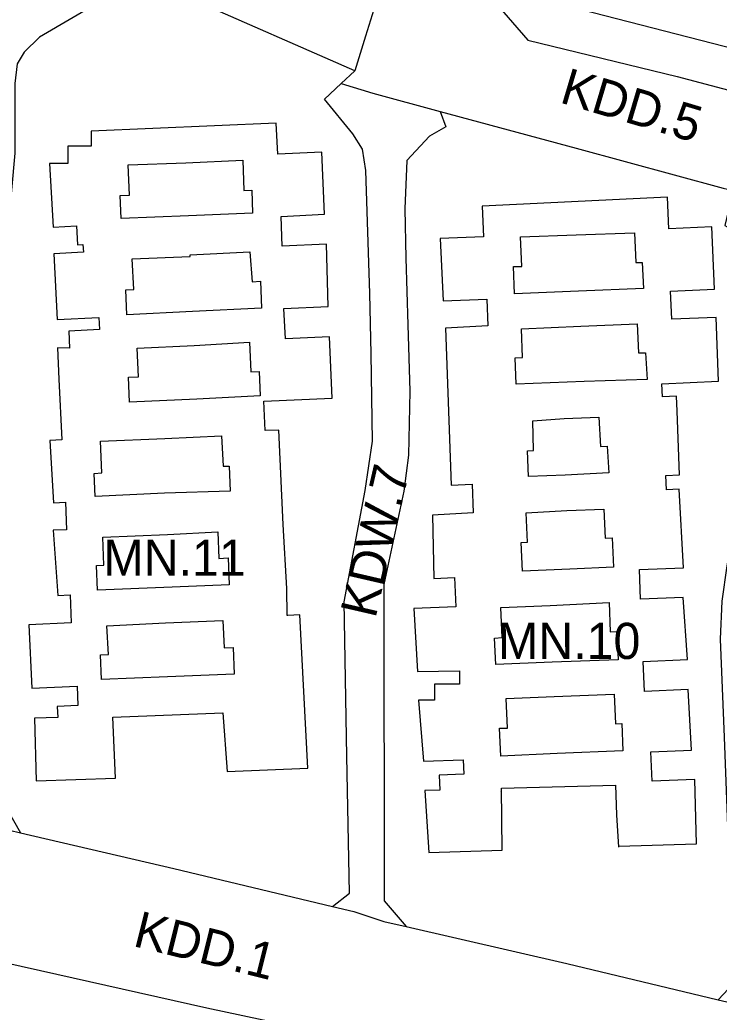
# Model space of a CAD drawing. Extents: x 7419601 to 7420547, y 5548907 to 5549873.
# Drawn here: x 7420033.1 to 7420129.8, y 5549175.5 to 5549312.7 of the extents above; entities that cross this region are included whole.
import ezdxf

# ---------------------------------------------------------------- set-up
doc = ezdxf.new("R2010")
doc.units = 0
for name, color, linetype in [('LIN_linie_rozgraniczajace', 7, 'Continuous'), ('LIN_nieprzekraczalna linia zabudowy', 7, 'Continuous'), ('LIN_obowiązująca linia zabudowy', 7, 'Continuous'), ('TXT_opisy_przeznaczen', 7, 'Continuous')]:
    doc.layers.add(name, color=color, linetype=linetype)

msp = doc.modelspace()

# ---------------------------------------------------------------- linework, layer by layer
at = {"layer": 'LIN_linie_rozgraniczajace'}
msp.add_line((7420079.31, 5549189.43), (7420083.48, 5549188.06), dxfattribs=at)
for points in [[(7420127.71, 5549409.49), (7420126.91, 5549406.83), (7420119.09, 5549380.8), (7420109.98, 5549352.28), (7420104.74, 5549335.4), (7420098.57, 5549315.47), (7420103.37, 5549309.87)], [(7420048.72, 5549317.81), (7420035.84, 5549310.28), (7420033.75, 5549308.2), (7420032.79, 5549306.6), (7420032.47, 5549303.85), (7420032.44, 5549294.24), (7420030.96, 5549277.87), (7420028.44, 5549250.88), (7420029.48, 5549227.98), (7420030.53, 5549205.08), (7420033.23, 5549200.31)], [(7420079.46, 5549305.62), (7420056.72, 5549315.6), (7420048.72, 5549317.81)], [(7420082.77, 5549316.37), (7420080.94, 5549310.43), (7420079.46, 5549305.62)], [(7420103.37, 5549309.87), (7420124.03, 5549304.85), (7420136.57, 5549301.5), (7420141.49, 5549300.23)], [(7420076.37, 5549190.13), (7420078.73, 5549191.96), (7420078.38, 5549210.89), (7420077.97, 5549232.25), (7420080.91, 5549247.64), (7420081.9, 5549254.43), (7420081.71, 5549266.53), (7420081.52, 5549274.83), (7420081, 5549291.86), (7420080.54, 5549294.81), (7420079.21, 5549296.92), (7420075.26, 5549301.7), (7420077.57, 5549303.86), (7420079.46, 5549305.62)], [(7420077.57, 5549303.86), (7420081.94, 5549302.55), (7420091.26, 5549300.02)], [(7420091.26, 5549300.02), (7420092.07, 5549297.89), (7420089.77, 5549296.59), (7420086.67, 5549293.21), (7420086.37, 5549286.56), (7420086.5, 5549279.71), (7420086.78, 5549270.53), (7420087.05, 5549261.36), (7420086.9, 5549252.48), (7420086.25, 5549247.53), (7420083.5, 5549234.63), (7420083.52, 5549190.89), (7420086.58, 5549187.35)], [(7420091.26, 5549300.02), (7420110.06, 5549294.92), (7420130.41, 5549289.41), (7420131.78, 5549289.09), (7420133.94, 5549288.58)], [(7420131.78, 5549289.09), (7420130.64, 5549284.24), (7420134.19, 5549282.23), (7420134.3, 5549277.16), (7420134.49, 5549267.77), (7420134.69, 5549258.38), (7420132.79, 5549247.8), (7420130.9, 5549237.22), (7420130.22, 5549232.3), (7420130, 5549227.05), (7420130.53, 5549213.54), (7420130.9, 5549203.7), (7420131.27, 5549193.86), (7420131.83, 5549179.46), (7420129.69, 5549177.2)], [(7420084.89, 5549170.3), (7420078.89, 5549171.67), (7420068.95, 5549173.94), (7420058.99, 5549176.05), (7420010.3, 5549186.99), (7419973.64, 5549195.23), (7419934.39, 5549204.06), (7419932.6, 5549204.46)], [(7420030.16, 5549201.02), (7420033.23, 5549200.31), (7420054.44, 5549195.37), (7420076.37, 5549190.13), (7420079.31, 5549189.43)], [(7420083.48, 5549188.06), (7420086.58, 5549187.35), (7420108.79, 5549182.25), (7420129.69, 5549177.2), (7420138.71, 5549175.15)]]:
    msp.add_lwpolyline(points, dxfattribs=at)
at = {"layer": 'LIN_nieprzekraczalna linia zabudowy'}
msp.add_lwpolyline([(7420105.79, 5549315.41), (7420137.18, 5549307.31)], dxfattribs=at)
at = {"layer": 'LIN_obowiązująca linia zabudowy'}
for p, q in [((7420068.59, 5549298.37), (7420043, 5549297.29)), ((7420068.83, 5549294.12), (7420068.59, 5549298.37)), ((7420043, 5549297.29), (7420043, 5549295.23)), ((7420043, 5549295.23), (7420039.79, 5549295.23)), ((7420039.79, 5549295.23), (7420039.79, 5549292.83)), ((7420074.9, 5549294.38), (7420068.83, 5549294.12)), ((7420075.25, 5549285.79), (7420074.9, 5549294.38)), ((7420039.79, 5549292.83), (7420037.23, 5549292.82)), ((7420037.23, 5549292.82), (7420037.75, 5549284.03)), ((7420122.7, 5549288.14), (7420097.09, 5549286.92)), ((7420122.9, 5549283.8), (7420122.7, 5549288.14)), ((7420069.27, 5549285.51), (7420075.25, 5549285.79)), ((7420097.09, 5549286.92), (7420097.25, 5549282.68)), ((7420069.42, 5549281.39), (7420069.27, 5549285.51)), ((7420037.75, 5549284.03), (7420040.98, 5549284.18)), ((7420040.98, 5549284.18), (7420041.12, 5549281.59)), ((7420128.83, 5549284.08), (7420122.9, 5549283.8)), ((7420129.2, 5549275.44), (7420128.83, 5549284.08)), ((7420075.53, 5549281.66), (7420069.42, 5549281.39)), ((7420075.8, 5549273.07), (7420075.53, 5549281.66)), ((7420097.25, 5549282.68), (7420091.27, 5549282.43)), ((7420091.27, 5549282.43), (7420091.66, 5549273.82)), ((7420041.93, 5549280.57), (7420037.84, 5549280.34)), ((7420037.84, 5549280.34), (7420038.3, 5549271.24)), ((7420041.12, 5549281.59), (7420041.87, 5549281.63)), ((7420041.87, 5549281.63), (7420041.93, 5549280.57)), ((7420123.12, 5549275.18), (7420129.2, 5549275.44)), ((7420123.32, 5549271.3), (7420123.12, 5549275.18)), ((7420091.66, 5549273.82), (7420097.7, 5549274.08)), ((7420097.7, 5549274.08), (7420097.88, 5549270.39)), ((7420069.66, 5549272.77), (7420075.8, 5549273.07)), ((7420069.86, 5549268.6), (7420069.66, 5549272.77)), ((7420038.3, 5549271.24), (7420044.06, 5549271.52)), ((7420044.06, 5549271.52), (7420044.14, 5549269.85)), ((7420129.43, 5549271.52), (7420123.32, 5549271.3)), ((7420129.76, 5549262.73), (7420129.43, 5549271.52)), ((7420044.14, 5549269.85), (7420039.92, 5549269.64)), ((7420039.92, 5549269.64), (7420040.03, 5549267.3)), ((7420097.88, 5549270.39), (7420092.01, 5549270.07)), ((7420092.01, 5549270.07), (7420092.78, 5549248.35)), ((7420075.98, 5549268.85), (7420069.86, 5549268.6)), ((7420076.31, 5549260.38), (7420075.98, 5549268.85)), ((7420040.03, 5549267.3), (7420038.35, 5549267.32)), ((7420038.35, 5549267.32), (7420038.52, 5549263.02)), ((7420038.52, 5549263.02), (7420038.95, 5549254.61)), ((7420121.94, 5549262.38), (7420129.76, 5549262.73)), ((7420122, 5549260.55), (7420121.94, 5549262.38)), ((7420066.9, 5549259.96), (7420076.31, 5549260.38)), ((7420067.08, 5549255.89), (7420066.9, 5549259.96)), ((7420123.97, 5549260.66), (7420122, 5549260.55)), ((7420124.04, 5549258.58), (7420123.97, 5549260.66)), ((7420124.34, 5549249.78), (7420124.04, 5549258.58)), ((7420068.95, 5549255.97), (7420067.08, 5549255.89)), ((7420069.55, 5549242.91), (7420068.95, 5549255.97)), ((7420038.95, 5549254.61), (7420037.31, 5549254.55)), ((7420037.31, 5549254.55), (7420037.79, 5549245.92)), ((7420122.47, 5549249.71), (7420124.34, 5549249.78)), ((7420122.55, 5549247.71), (7420122.47, 5549249.71)), ((7420092.78, 5549248.35), (7420095.68, 5549248.49)), ((7420095.68, 5549248.49), (7420095.84, 5549244.54)), ((7420124.33, 5549247.78), (7420122.55, 5549247.71)), ((7420124.9, 5549236.95), (7420124.33, 5549247.78)), ((7420037.79, 5549245.92), (7420039.45, 5549246)), ((7420039.45, 5549246), (7420039.61, 5549242.19)), ((7420095.84, 5549244.54), (7420090.22, 5549244.19)), ((7420090.22, 5549244.19), (7420090.41, 5549235.47)), ((7420039.61, 5549242.19), (7420037.76, 5549242.12)), ((7420037.76, 5549242.12), (7420038.39, 5549233.12)), ((7420070.07, 5549234.09), (7420069.55, 5549242.91)), ((7420118.81, 5549236.69), (7420124.9, 5549236.95)), ((7420118.98, 5549232.58), (7420118.81, 5549236.69)), ((7420090.41, 5549235.47), (7420093.24, 5549235.59)), ((7420093.24, 5549235.59), (7420093.43, 5549231.55)), ((7420070.1, 5549230.34), (7420070.07, 5549234.09)), ((7420038.39, 5549233.12), (7420040.09, 5549233.2)), ((7420040.09, 5549233.2), (7420040.25, 5549229.33)), ((7420124.89, 5549232.85), (7420118.98, 5549232.58)), ((7420125.49, 5549224.25), (7420124.89, 5549232.85)), ((7420093.43, 5549231.55), (7420087.61, 5549231.31)), ((7420087.61, 5549231.31), (7420088.13, 5549222.58)), ((7420070.22, 5549230.34), (7420070.1, 5549230.34)), ((7420071.84, 5549230.43), (7420070.22, 5549230.34)), ((7420072.98, 5549209.25), (7420071.84, 5549230.43)), ((7420040.25, 5549229.33), (7420034.41, 5549229.05)), ((7420034.41, 5549229.05), (7420034.79, 5549220.29)), ((7420119.34, 5549224), (7420125.49, 5549224.25)), ((7420088.13, 5549222.58), (7420093.95, 5549222.67)), ((7420093.95, 5549222.67), (7420093.95, 5549220.87)), ((7420119.51, 5549219.85), (7420119.34, 5549224)), ((7420034.79, 5549220.29), (7420041.05, 5549220.59)), ((7420041.05, 5549220.59), (7420041.18, 5549217.91)), ((7420093.95, 5549220.87), (7420090.49, 5549220.87)), ((7420090.49, 5549220.87), (7420090.49, 5549218.66)), ((7420125.56, 5549220.09), (7420119.51, 5549219.85)), ((7420126.03, 5549211.71), (7420125.56, 5549220.09)), ((7420090.49, 5549218.66), (7420088.27, 5549218.66)), ((7420088.27, 5549218.66), (7420088.94, 5549210.19)), ((7420041.18, 5549217.91), (7420038.31, 5549217.77)), ((7420038.31, 5549217.77), (7420038.38, 5549216.23)), ((7420038.38, 5549216.23), (7420035.16, 5549216.16)), ((7420035.16, 5549216.16), (7420035.41, 5549207.48)), ((7420046.01, 5549216.31), (7420061.22, 5549216.9)), ((7420046.35, 5549207.88), (7420046.01, 5549216.31)), ((7420061.22, 5549216.9), (7420061.79, 5549208.8)), ((7420120.39, 5549211.48), (7420126.03, 5549211.71)), ((7420088.94, 5549210.19), (7420094.47, 5549210.41)), ((7420094.47, 5549210.41), (7420094.55, 5549208.43)), ((7420120.56, 5549207.42), (7420120.39, 5549211.48)), ((7420061.79, 5549208.8), (7420072.98, 5549209.25)), ((7420035.41, 5549207.48), (7420046.35, 5549207.88)), ((7420094.55, 5549208.43), (7420091.15, 5549208.29)), ((7420091.15, 5549208.29), (7420091.24, 5549206.22)), ((7420126.46, 5549207.66), (7420120.56, 5549207.42)), ((7420126.72, 5549198.77), (7420126.46, 5549207.66)), ((7420091.24, 5549206.22), (7420089.16, 5549206.14)), ((7420099.75, 5549206.46), (7420115.53, 5549206.9)), ((7420099.82, 5549197.89), (7420099.75, 5549206.46)), ((7420115.53, 5549206.9), (7420115.64, 5549202.79)), ((7420089.16, 5549206.14), (7420089.72, 5549197.57)), ((7420099.56, 5549206.02), (7420099.56, 5549206.02)), ((7420115.64, 5549202.79), (7420115.95, 5549198.34)), ((7420115.98, 5549198.44), (7420126.72, 5549198.77)), ((7420089.72, 5549197.57), (7420099.82, 5549197.89))]:
    msp.add_line(p, q, dxfattribs=at)
for points in [[(7420047.16, 5549285.21), (7420047.03, 5549288.38), (7420048.29, 5549288.44), (7420048.12, 5549292.65), (7420056.11, 5549292.92), (7420063.96, 5549293.28), (7420064.1, 5549289.1), (7420065.21, 5549289.14), (7420065.3, 5549285.94), (7420056.47, 5549285.59)], [(7420101.53, 5549274.79), (7420101.43, 5549278.56), (7420102.55, 5549278.6), (7420102.39, 5549282.67), (7420110.07, 5549282.96), (7420118.16, 5549283.21), (7420118.33, 5549279.11), (7420119.2, 5549279.11), (7420119.37, 5549275.52), (7420110.41, 5549275.16)], [(7420048.89, 5549275.4), (7420048.67, 5549279.63), (7420056.71, 5549279.98), (7420056.7, 5549280.17), (7420064.97, 5549280.62), (7420065.25, 5549276.48), (7420066.4, 5549276.54), (7420066.58, 5549272.84), (7420057.04, 5549272.35), (7420047.94, 5549271.89), (7420047.79, 5549275.35)], [(7420101.79, 5549262.3), (7420101.63, 5549265.96), (7420102.66, 5549266), (7420102.52, 5549269.95), (7420110.7, 5549270.31), (7420118.52, 5549270.64), (7420118.69, 5549266.64), (7420119.68, 5549266.63), (7420119.88, 5549262.97), (7420111.19, 5549262.68)], [(7420048.33, 5549259.82), (7420048.19, 5549263.26), (7420049.55, 5549263.32), (7420049.39, 5549267.28), (7420057.26, 5549267.65), (7420064.89, 5549268.1), (7420065.08, 5549264.03), (7420066.26, 5549264.08), (7420066.39, 5549260.71), (7420057.61, 5549260.23)], [(7420103.46, 5549249.54), (7420103.33, 5549253.11), (7420104.17, 5549253.14), (7420104.08, 5549257.25), (7420108.41, 5549257.58), (7420113.22, 5549257.76), (7420113.45, 5549253.7), (7420114.38, 5549253.75), (7420114.58, 5549250.05), (7420108.55, 5549249.73)], [(7420044.31, 5549254.42), (7420053.2, 5549254.82), (7420061.03, 5549255.17), (7420061.25, 5549250.97), (7420062.07, 5549251), (7420062.21, 5549247.54), (7420053.13, 5549247.24), (7420043.57, 5549246.78), (7420043.41, 5549249.99), (7420044.46, 5549250.04)], [(7420102.65, 5549236.48), (7420102.49, 5549240.44), (7420103.33, 5549240.48), (7420103.17, 5549244.53), (7420108.77, 5549244.84), (7420113.88, 5549245.04), (7420114.07, 5549241.03), (7420115.06, 5549241.07), (7420115.24, 5549237), (7420109.18, 5549236.75)], [(7420044.62, 5549241.18), (7420053.56, 5549241.55), (7420060.51, 5549241.92), (7420060.67, 5549238.23), (7420061.97, 5549238.3), (7420062.11, 5549234.58), (7420054.19, 5549234.26), (7420043.87, 5549233.84), (7420043.73, 5549237.23), (7420044.78, 5549237.28)], [(7420098.95, 5549223.56), (7420098.8, 5549227.23), (7420099.82, 5549227.28), (7420099.65, 5549231.46), (7420106.47, 5549231.74), (7420114.63, 5549232.14), (7420114.79, 5549228.07), (7420115.69, 5549228.11), (7420115.87, 5549224.21), (7420106.77, 5549223.87)], [(7420045.17, 5549228.93), (7420053.29, 5549229.33), (7420061.23, 5549229.66), (7420061.38, 5549225.86), (7420062.62, 5549225.9), (7420062.76, 5549222.22), (7420053.57, 5549221.85), (7420044.42, 5549221.48), (7420044.28, 5549224.91), (7420045.39, 5549224.96)], [(7420099.64, 5549210.9), (7420099.48, 5549214.75), (7420100.57, 5549214.79), (7420100.41, 5549218.89), (7420107.02, 5549219.15), (7420115.33, 5549219.48), (7420115.53, 5549215.37), (7420116.38, 5549215.4), (7420116.54, 5549211.62), (7420107.46, 5549211.26)]]:
    msp.add_lwpolyline(points, close=True, dxfattribs=at)

# ---------------------------------------------------------------- texts
at = {"layer": 'TXT_opisy_przeznaczen'}
for s, rotation, p in [('KDD.5', 343.4242, (7420107.64, 5549301.29)), ('KDW.7', 77, (7420082.31, 5549229.82)), ('KDD.1', 346.0422, (7420048.64, 5549184.69))]:
    msp.add_text(s, height=5, rotation=rotation, dxfattribs=at).set_placement(p)
for s, p in [('MN.11', (7420044.69, 5549235.83)), ('MN.10', (7420099.26, 5549224.33))]:
    msp.add_text(s, height=5, dxfattribs=at).set_placement(p)

doc.saveas('drawing.dxf')
